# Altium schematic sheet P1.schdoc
size 381 x 305 mm; Symbol: Drawing-Symbol_A4; Company: 嘉立创EDA; Version: V1.0; Page Size: A4; @Project Name: foc; @Update Date: 2026-06-04; @Create Date: 2026-06-04; Device: Drawing-Symbol_A4; @Board Name: Board1; @Page Name: P1; @Create Time: 11:16:55; @Page Count: 1; @Page No: 1; @Schematic Name: Schematic1; @Update Time: 12:06:55; @Assembly Variant: Basic; Border: 1; Title Block Position: 3; Size: A4; Width: 1500; Height: 1200; Region Start: 1; X Region Count: 6; Y Region Count: 4; Blade Width: 10
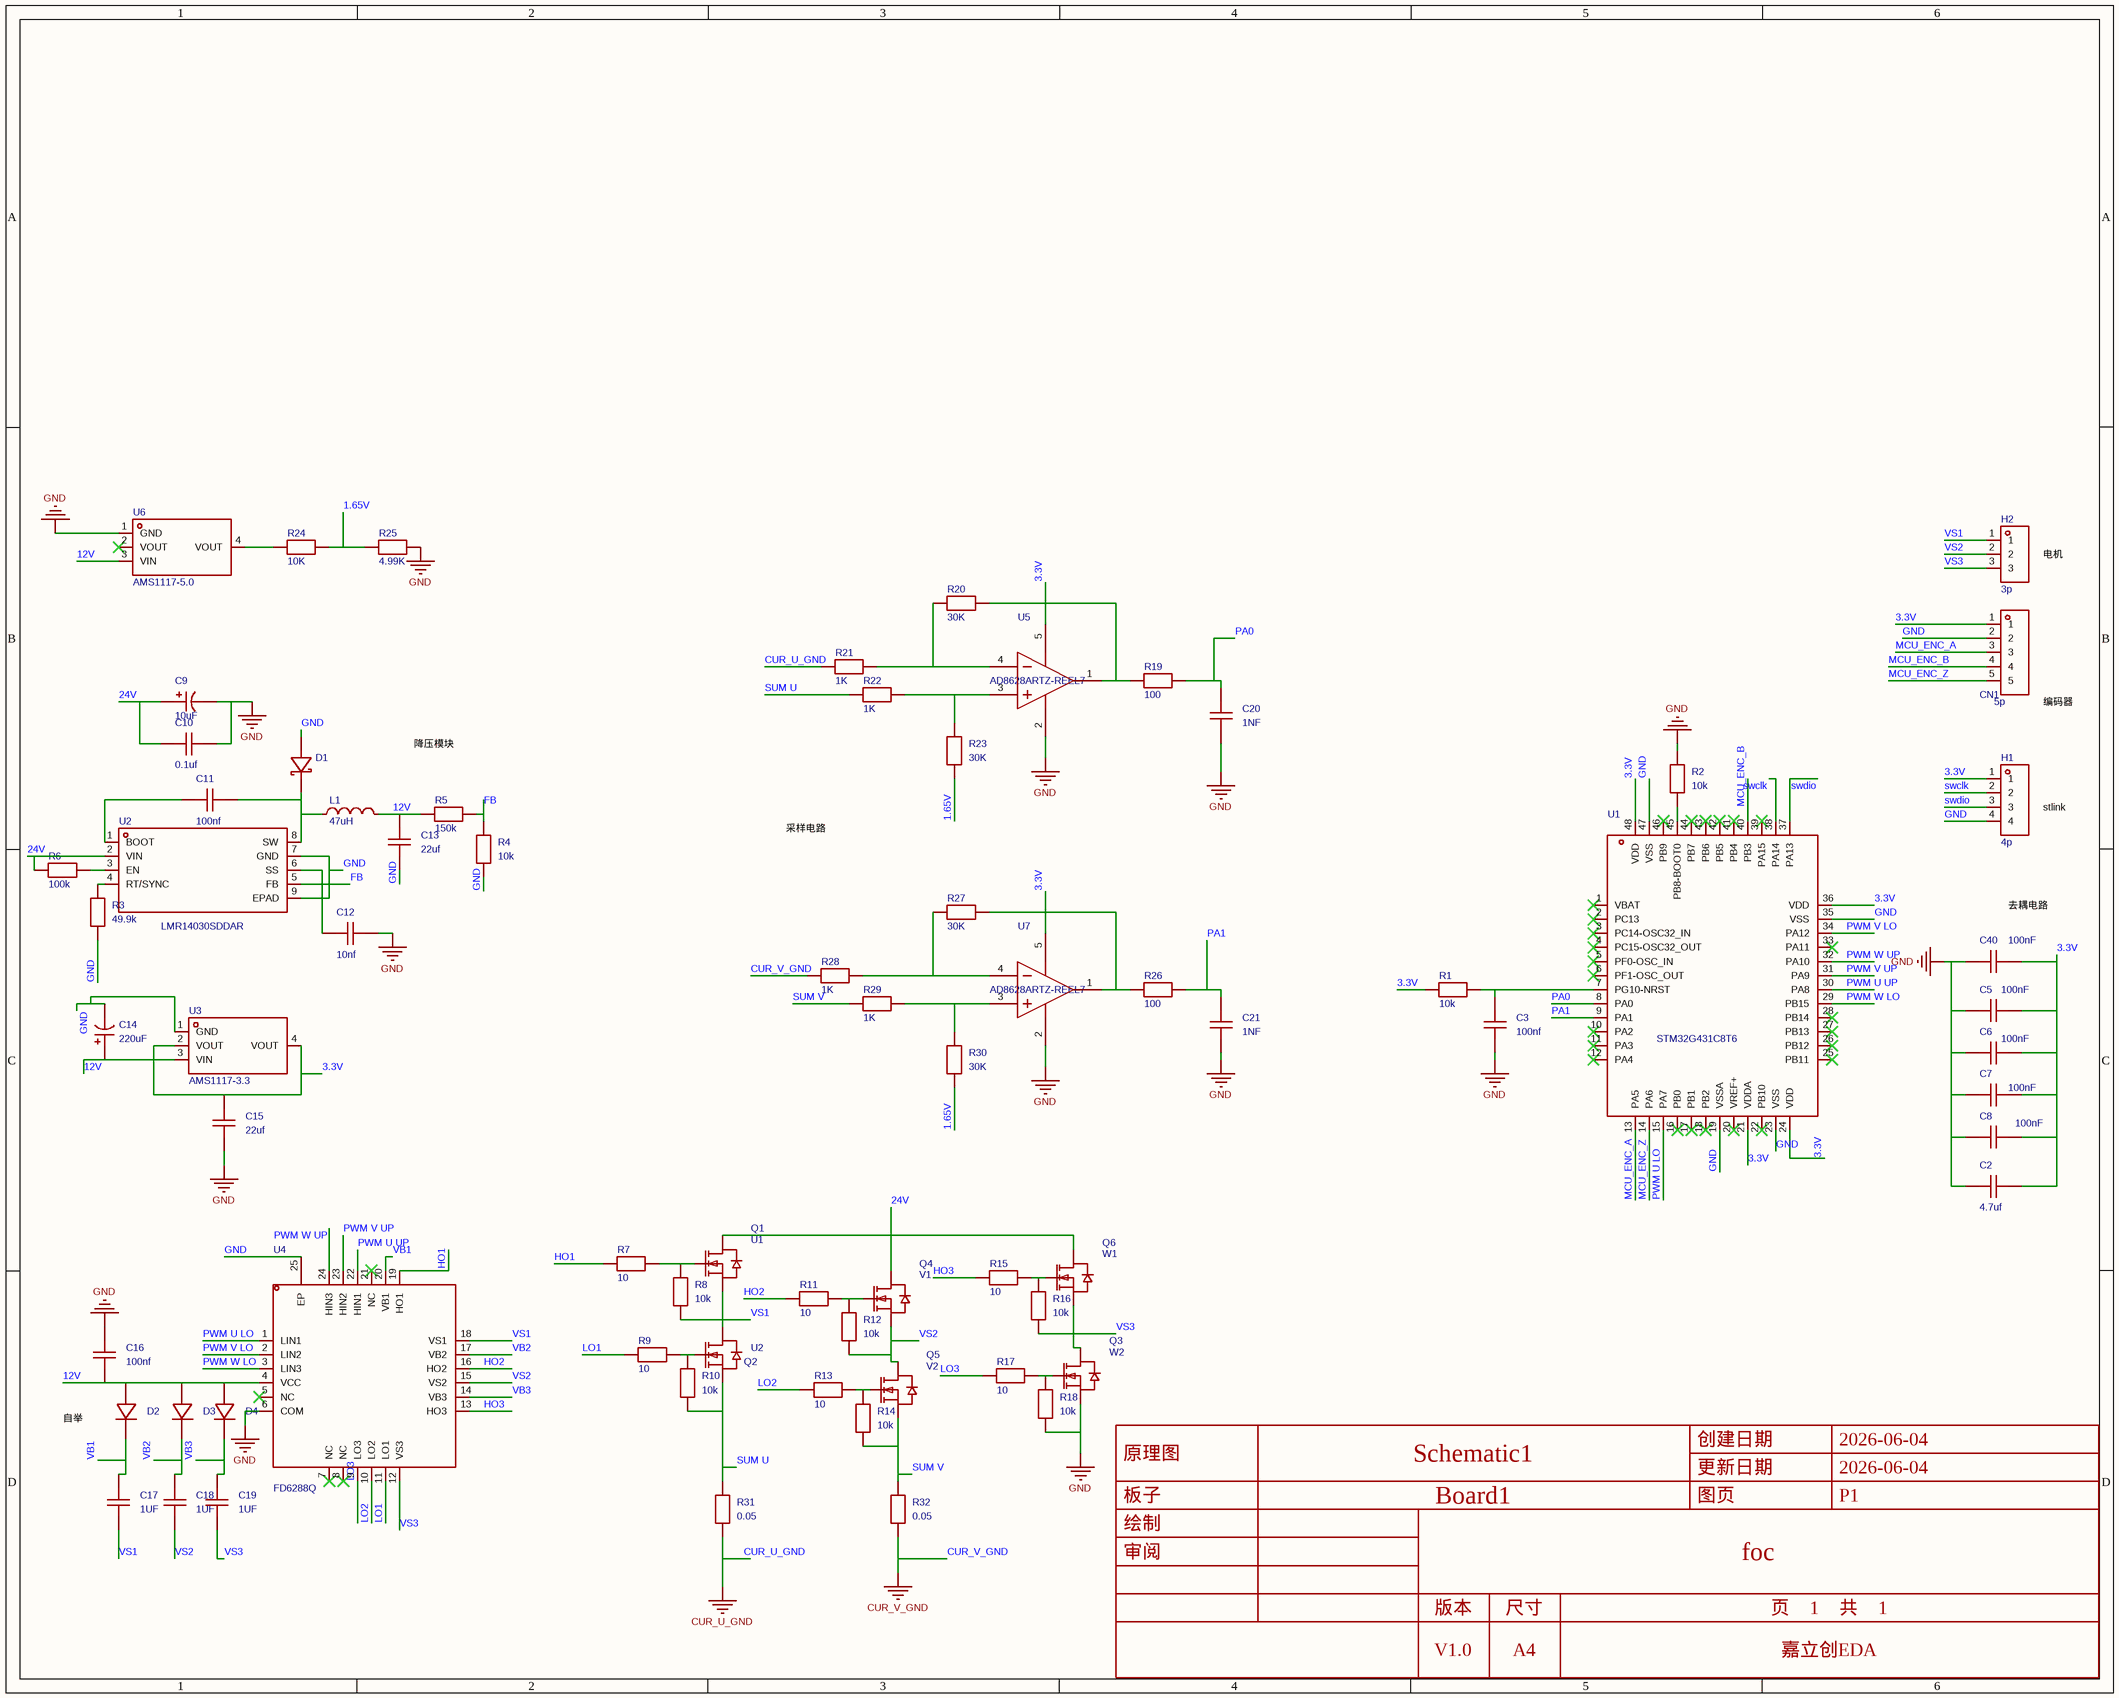
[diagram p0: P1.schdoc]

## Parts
C2  4.7uf  [C0603]
C3  100nf  [C0603]
C5  100nF  [C0603]
C6  100nF  [C0603]
C7  100nF  [C0603]
C8  100nF  [C0603]
C9  10uF  [CAP-SMD_BD6.3-L6.6-W6.6-LS7.3-FD-H7.7]
C10  0.1uf  [C0603]
C11  100nf  [C0603]
C12  10nf  [C0603]
C13  22uf  [C0603]
C14  220uF  [CAP-SMD_L7.3-W4.3-RD]
C15  22uf  [C0603]
C16  100nf  [C0603]
C17  1UF  [C0603]
C18  1UF  [C0603]
C19  1UF  [C0603]
C20  1NF  [C0603]
C21  1NF  [C0603]
C40  100nF  [C0603]
CN1  5p  [CONN-TH_5P-P2.50_WAFER-XH254Z-5A]
D1  (no value)  [SMA_L4.2-W2.6-LS5.0-RD]
D2  (no value)  [SOD-123_L2.8-W1.8-LS3.7-RD]
D3  (no value)  [SOD-123_L2.8-W1.8-LS3.7-RD]
D4  (no value)  [SOD-123_L2.8-W1.8-LS3.7-RD]
H1  4p  [HDR-TH_4P-P2.54-V-M]
H2  3p  [HDR-TH_3P-P2.54-V-M_PZ254V-11-03P]
L1  47uH  [L0603]
Q1  U1  [TO-252-2_L6.6-W6.1-P4.57-LS9.9-BR-CW]
Q2  U2  [TO-252-2_L6.6-W6.1-P4.57-LS9.9-BR-CW]
Q3  W2  [TO-252-2_L6.6-W6.1-P4.57-LS9.9-BR-CW]
Q4  V1  [TO-252-2_L6.6-W6.1-P4.57-LS9.9-BR-CW]
Q5  V2  [TO-252-2_L6.6-W6.1-P4.57-LS9.9-BR-CW]
Q6  W1  [TO-252-2_L6.6-W6.1-P4.57-LS9.9-BR-CW]
R1  10k  [R1206]
R2  10k  [R1206]
R3  49.9k  [R1206]
R4  10k  [R1206]
R5  150k  [R1206]
R6  100k  [R1206]
R7  10  [R1206]
R8  10k  [R1206]
R9  10  [R1206]
R10  10k  [R1206]
R11  10  [R1206]
R12  10k  [R1206]
R13  10  [R1206]
R14  10k  [R1206]
R15  10  [R1206]
R16  10k  [R1206]
R17  10  [R1206]
R18  10k  [R1206]
R19  100  [R1206]
R20  30K  [R1206]
R21  1K  [R1206]
R22  1K  [R1206]
R23  30K  [R1206]
R24  10K  [R1206]
R25  4.99K  [R1206]
R26  100  [R1206]
R27  30K  [R1206]
R28  1K  [R1206]
R29  1K  [R1206]
R30  30K  [R1206]
R31  0.05  [R1206]
R32  0.05  [R1206]
U1  STM32G431C8T6  [LQFP-48_L7.0-W7.0-P0.50-LS9.0-BL]
U2  LMR14030SDDAR  [SO-8_L4.9-W3.9-P1.27-LS6.0-BL-EP]
U3  AMS1117-3.3  [SOT-223-3_L6.5-W3.4-P2.30-LS7.0-BR]
U4  FD6288Q  [QFN-24_L4.0-W4.0-P0.50-BL-EP2.6]
U5  AD8628ARTZ-REEL7  [SOT-23-5_L3.0-W1.7-P0.95-LS2.8-BR]
U6  AMS1117-5.0  [SOT-223_L6.5-W3.5-P2.30-LS7.0-BR]
U7  AD8628ARTZ-REEL7  [SOT-23-5_L3.0-W1.7-P0.95-LS2.8-BR]

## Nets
CUR_U_GND: R21.1 R31.1
CUR_V_GND: R28.1 R32.1
GND: C2.1 C3.1 C5.1 C6.1 C7.1 C8.1 C9.2 C10.1 C12.1 C13.2 C14.2 C15.2 C16.1 C20.2 C21.2 C40.1 CN1.2 D1.2(+) H1.4 Q3.3(S) R2.2 R3.1 R4.1 R18.1 R25.2 U1.19(VSSA) U1.23(VSS) U1.35(VSS) U1.47(VSS) U2.7(GND) U2.9(EPAD) U3.1(GND) U4.6(COM) U4.25(EP) U5.2(-V) U6.1(GND) U7.2(-V)
1.65V: R23.2 R24.2 R25.1 R30.2
3.3V: C2.2 C5.2 C6.2 C7.2 C8.2 C15.1 C40.2 CN1.1 H1.1 R1.1 U1.21(VDDA) U1.24(VDD) U1.36(VDD) U1.48(VDD) U3.2(VOUT) U3.4(VOUT) U5.5(+V) U7.5(+V)
12V: C13.1 C14.1 C16.2 D2.2(A) D3.2(A) D4.2(A) L1.2 R5.1 U3.3(VIN) U4.4(VCC) U6.3(VIN)
24V: C9.1 C10.2 Q1.2(D) Q4.2(D) Q6.2(D) R6.1 U2.2(VIN)
FB: R4.2 R5.2 U2.5(FB)
HO1: R7.2 U4.19(HO1)
HO2: R11.2 U4.16(HO2)
HO3: R15.2 U4.13(HO3)
LO1: R9.2 U4.11(LO1)
LO2: R13.2 U4.10(LO2)
LO3: R17.2 U4.9(LO3)
MCU_ENC_A: CN1.3 U1.13(PA5)
MCU_ENC_B: CN1.4 U1.40(PB3)
MCU_ENC_Z: CN1.5 U1.14(PA6)
PA0: C20.1 R19.1 U1.8(PA0)
PA1: C21.1 R26.1 U1.9(PA1)
PWM U LO: U1.15(PA7) U4.1(LIN1)
PWM U UP: U1.30(PA8) U4.22(HIN1)
PWM V LO: U1.34(PA12) U4.2(LIN2)
PWM V UP: U1.31(PA9) U4.23(HIN2)
PWM W LO: U1.29(PB15) U4.3(LIN3)
PWM W UP: U1.32(PA10) U4.24(HIN3)
SUM U: Q2.3(S) R10.1 R22.2 R31.2
SUM V: Q5.3(S) R14.1 R29.2 R32.2
swclk: H1.2 U1.38(PA14)
swdio: H1.3 U1.37(PA13)
VB1: C17.1 D2.1(K) U4.20(VB1)
VB2: C18.1 D3.1(K) U4.17(VB2)
VB3: C19.1 D4.1(K) U4.14(VB3)
VS1: C17.2 H2.1 Q1.3(S) Q2.2(D) R8.1 U4.18(VS1)
VS2: C18.2 H2.2 Q4.3(S) Q5.2(D) R12.1 U4.15(VS2)
VS3: C19.2 H2.3 Q3.2(D) Q6.3(S) R16.1 U4.12(VS3)
NetC3_2: C3.2 R1.2 U1.7(PG10-NRST)
NetC11_1: C11.1 D1.1(-) L1.1 U2.8(SW)
NetC11_2: C11.2 U2.1(BOOT)
NetC12_2: C12.2 U2.6(SS)
NetQ1_1: Q1.1(G) R7.1 R8.2
NetQ2_1: Q2.1(G) R9.1 R10.2
NetQ3_1: Q3.1(G) R17.1 R18.2
NetQ4_1: Q4.1(G) R11.1 R12.2
NetQ5_1: Q5.1(G) R13.1 R14.2
NetQ6_1: Q6.1(G) R15.1 R16.2
NetR2_1: R2.1 U1.45(PB8-BOOT0)
NetR3_2: R3.2 U2.4(RT/SYNC)
NetR6_2: R6.2 U2.3(EN)
NetR19_2: R19.2 R20.1 U5.1(OUT)
NetR20_2: R20.2 R21.2 U5.4(-IN)
NetR22_1: R22.1 R23.1 U5.3(+IN)
NetR24_1: R24.1 U6.4(VOUT)
NetR26_2: R26.2 R27.1 U7.1(OUT)
NetR27_2: R27.2 R28.2 U7.4(-IN)
NetR29_1: R29.1 R30.1 U7.3(+IN)

Not connected (* = marked no-connect by the designer): U1 1(VBAT)* 2(PC13)* 3(PC14-OSC32_IN)* 4(PC15-OSC32_OUT)* 5(PF0-OSC_IN)* 6(PF1-OSC_OUT)* 10(PA2)* 11(PA3)* 12(PA4)* 16(PB0)* 17(PB1)* 18(PB2)* 20(VREF+)* 22(PB10)* 25(PB11)* 26(PB12)* 27(PB13)* 28(PB14)* 33(PA11)* 39(PA15)* 41(PB4)* 42(PB5)* 43(PB6)* 44(PB7)* 46(PB9)*; U4 5(NC)* 7(NC)* 8(NC)* 21(NC)*; U6 2(VOUT)*

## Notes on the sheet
- (near H2) 电机
- (near CN1) 编码器
- 降压模块
- (near H1) stlink
- 采样电路
- (near C40) 去耦电路
- 自举

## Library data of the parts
C2 C3 C5-C8 C10-C13 C15-C21 C40 = CAP_0603: Symbol: Capacitance; ConvertToPcb: yes; ModelId: ac125912035d415993ca9572d50418b10819f05c4eef4c71ace90d822a990e87; ModelName: C0603_L1.6-W0.8-H0.8; ModelTransform: 62.992,31.496,0,0,0,0,0,0,0
C9 = JVJ50V100M6x8: 容值:100uF;精度:±20%;额定电压:50V;纹波电流:140mA@120Hz;; Manufacturer: JIERR(捷而瑞); AddInBom: yes; ModelId: ccbda52dceed4b139172c40f75c9da3f0819f05c4eef4c71ace90d822a990e87; ModelTransform: 287.401,259.842,0,0,0,0,0,0,0; Tolerance: ±20%; Voltage Rating: 50V; Lifetime: 2000hrs@105℃
C14 = TA10R0L220AR30: 容值:220uF;精度:-30%~+10%;额定电压:10V;等效串联电阻(ESR):30mΩ@100kHz;; Manufacturer: JIERR(捷而瑞); AddInBom: yes; ModelId: 8a83722128254b9eb218ad9f7deffbeb0819f05c4eef4c71ace90d822a990e87; ModelTransform: 288.976,169.291,0,180,0,0,0,0,0; Voltage Rating: 10V; Current - Leakage: 220uA@20℃,2min; Ripple Current: 2.2A@100kHz
CN1 = WAFER-XH254Z-5AL: 插针结构:1x5P;间距:2.54mm;安装方式:直插;参考系列:XH;总PIN数:5P;排数:1;每排PIN数:5;额定电流:3A;触头材质:黄铜;工作温度:-25℃~+85℃;; Manufacturer: HANBO(汉博); AddInBom: yes; ModelId: 79b08f5d88c847b5a19023d5cc77e9220819f05c4eef4c71ace90d822a990e87; ModelTransform: 590.554,232.28296,0,0,0,0,0,15.748,-133.858; Pins Structure: 1x5P; Pitch: 2.54mm; Reference Series: XH; Number of PINs Per Row: 5; Current Rating: 3A; Voltage Rating: 250V; Plastic Material: PA66; Flame Retardant Rating: UL94V-0
D1 = SS34-E: 正向压降(Vf):600mV@3A;直流反向耐压(Vr):40V;整流电流:3A;; Manufacturer: MDD(辰达半导体); AddInBom: yes; ModelId: d417df25dbfe400cb6fd237f79dd97960819f05c4eef4c71ace90d822a990e87; ModelTransform: 196.85,101.181,0,0,0,0,0,0,0; Voltage - DC Reverse(Vr): 40V; Current - Rectified: 3A; Reverse Leakage Current (Ir): 500uA@40V; Operating Junction Temperature Range: -55℃~+125℃; Non-Repetitive Peak Forward Surge Current: 75A
D2-D4 = 1N4148W-E3-08: 二极管配置:1个独立式;正向压降(Vf):1.2V@100mA;直流反向耐压(Vr):75V;整流电流:150mA;反向恢复时间(Trr):4ns;; Manufacturer: VISHAY(威世); AddInBom: yes; ModelId: 7884390a25fb4c08947731ebfba7e3f80819f05c4eef4c71ace90d822a990e87; ModelTransform: 144.8816,62.992,0,0,0,0,0,0,0; Diode Configuration: 1个独立式; Voltage - DC Reverse(Vr): 75V; Current - Rectified: 150mA; Pd - Power Dissipation: 350mW; Reverse Leakage Current (Ir): 100uA@100V; Reverse Recovery Time (trr): 4ns; Non-Repetitive Peak Forward Surge Current: 2A
H1 = PZ254V-11-04P: 插针结构:1x4P;间距:2.54mm;行距:-;圆针/方针:方针;安装方式:直插;排数:单排;总PIN位数:4P;额定电流:3A;额定电压:250V;配合针长度:6mm;塑高:2.5mm;端接针长度:3mm;触头材质:-;工作温度:-40℃~+105℃;颜色:黑色;; Manufacturer: XFCN(兴飞); Symbol: PZ254V-11-04P_C2691448; AddInBom: yes; ModelId: 112f4d05e8d64e99ab9a333894bea4f90819f05c4eef4c71ace90d822a990e87; ModelName: HDR-TH_4P-P2.54-M-LI-1X4P; ModelTransform: 399.999,104.7242,0,0,0,0,0,0,-118.11; Pin Structure: 1x4P; Pitch: 2.54mm; Circluar Pins/Square Pins: 方针; Current Rating: 3A; Voltage Rating (Max): 250V
H2 = PZ254V-11-03P: 插针结构:1x3P;间距:2.54mm;行距:-;圆针/方针:方针;安装方式:直插;排数:单排;总PIN位数:3P;额定电流:3A;额定电压:250V;配合针长度:6mm;塑高:2.5mm;端接针长度:3mm;工作温度:-40℃~+105℃;颜色:黑色;; Manufacturer: XFCN(兴飞); Symbol: PZ254V-11-03P_C2937625; AddInBom: yes; ModelId: bd28a638fbd247be9398fd5d39c366ec0819f05c4eef4c71ace90d822a990e87; ModelTransform: 300.3931,100,0,0,0,0,0,0,-118.11; Pin Structure: 1x3P; Pitch: 2.54mm; Circluar Pins/Square Pins: 方针; Current Rating: 3A; Voltage Rating (Max): 250V
L1 = L_0603: Symbol: SDFL1608S100KTF; AddInBom: yes; ModelId: 2bc5ec593d464d6ba9807aec0b5673c20819f05c4eef4c71ace90d822a990e87; ModelName: L0603_L1.6-W0.8-H0.5_BEAD; ModelTransform: 62.992,31.496,0,180,0,0,0.094,0.629,0
Q1-Q6 = NCEP40T11K: 数量:1个N沟道;漏源电压(Vdss):40V;连续漏极电流(Id):110A;导通电阻(RDS(on)):3.3mΩ@4.5V,55A;耗散功率(Pd):150W;阈值电压(Vgs(th)):1.2V;; Manufacturer: NCE(无锡新洁能); AddInBom: yes; ModelId: ce57f84d66384067af8a68020b6de06d0819f05c4eef4c71ace90d822a990e87; ModelName: TO-252-2L-3P_L6.6-W6.1-H2.3-LS10.1-P4.6; ModelTransform: 259.842,390.52442,0,90,0,0,-39.39,0,0; Number: 1个N沟道; Drain to Source Voltage: 40V; Current - Continuous Drain(Id): 110A; Pd - Power Dissipation: 150W; Gate Threshold Voltage (Vgs(th)): 1.2V; Gate Charge(Qg): 60nC@20V; Input Capacitance(Ciss): 3.51nF@20V; Reverse Transfer Capacitance (Crss@Vds): 60pF
R1-R32 = RE1206F1R000: 电阻类型:采样电阻；合金电阻;阻值:0Ω;精度:±1%;功率:1W;安装方式:贴片;; Manufacturer: JIERR(捷而瑞); AddInBom: yes; ModelId: 89a1f13db2384da588040e0b3c55bf660819f05c4eef4c71ace90d822a990e87; ModelName: R1206_L3.2-W1.6-H0.6; ModelTransform: 125.984,62.992,0,0,0,0,0,0,0; Tolerance: ±1%; Power(Watts): 1W
U1 = STM32G431C8T6: CPU内核:ARM-M系列;CPU最大主频:170MHz;应用领域:-;; Manufacturer: ST(意法半导体); AddInBom: yes; ModelId: 093be70396ff421eb2cdb946d5311efc0819f05c4eef4c71ace90d822a990e87; ModelName: LQFP-48_L7.0-W7.0-H1.4-LS9.0-P0.50; ModelTransform: 354.331,354.331,0,0,0,0,0,0,0; CPU Maximum Speed: 170MHz; Program Storage Size: 64KB; Program Memory Type: FLASH; Number of I/O: 38; ADC (Bit): 12bit; Voltage - Supply: 1.71V~3.6V
U2 = LMR14030SDDAR: 功能类型:降压型;工作电压:4V~40V;输出电压:800mV~28V;输出电流:3.5A;输出类型:可调;; Manufacturer: TI(德州仪器); AddInBom: yes; ModelId: 756fba4e187a48c69a2c935cd5c4465b0819f05c4eef4c71ace90d822a990e87; ModelName: SO-8_L4.9-W3.9-H1.5-LS5.9-P1.27; ModelTransform: 240.39054,192.913,0,270,0,0,0.004,-0.002,0; Function: 降压型; Voltage - Supply: 4V~40V; Output Current: 3.5A; Frequency - Switching: 2.5MHz; Synchronous Rectifier: 否; Number of Outputs: 1; Topology: 降压式; Quiescent Current: 40uA; Switch tube (built-in/external): 内置; Output Type: 可调
U3 = AMS1117-3.3_C6186: 输出类型:固定;工作电压:15V;输出电压:3.3V;输出电流:1A;电源纹波抑制比(PSRR):72dB@(120Hz);输出极性:正极;; Manufacturer: AMS; AddInBom: yes; ModelId: 925194bf9823436183a3e0b978a8d0760819f05c4eef4c71ace90d822a990e87; ModelName: SOT-223-4P_L6.5-W3.5-H1.6-LS7.0-P2.30; ModelTransform: 279.89794,255.905,0,180,0,0,-3.9385,-0.0005,0; Output Type: 固定; Voltage - Supply: 15V; Output Voltage: 3.3V; Output Current: 1A; Voltage Dropout: 1.1V@(800mA); standby current: 5mA; Noise: 0.003%Vout; Output Configuration: 正极; Number of Outputs: 1
U4 = FD6288Q: 驱动配置:三相;负载类型:MOSFET；IGBT;驱动通道数:3;灌电流(IOL):1.8A;拉电流(IOH):1.5A;工作电压:5V~20V;上升时间(tr):12ns;下降时间(tf):12ns;; Manufacturer: Fortior Tech(峰岹); Symbol: FD6288Q_C328453; AddInBom: yes; ModelId: 1e6a51e223ba431598528b34e5bdfcc90819f05c4eef4c71ace90d822a990e87; ModelName: QFN-24_L4.0-W4.0-H0.9-P0.50; ModelTransform: 157.48,157.48,0,90,0,0,0,0,0; Driven Configuration: 三相; Number of Drivers: 3; Current - Output Low(IOL): 1.8A; Current - Output High(IOH): 1.5A; Voltage - Supply: 5V~20V; Rise Time: 12ns; Propagation Delay tpLH: 300ns; Propagation Delay tpHL: 100ns; Input Logic Level - High: 2.7V; Input Logic Level - Low: 800mV; Quiescent Current(Iq): 330uA
U5 U7 = AD8628ARTZ-REEL7: 放大器数:单路;增益带宽积(GBP):2.5MHz;输入偏置电流(Ib):30pA;输入失调电压(Vos):1uV;压摆率(SR):1V/us;带宽(-3db):2.5MHz;轨到轨:-;; Manufacturer: ADI(亚德诺); AddInBom: yes; ModelId: 0a2a1b8f50944f73965918ad6e5fe1670819f05c4eef4c71ace90d822a990e87; ModelName: SOT-23-5_L2.9-W1.6-H1.1-LS2.8-P0.95; ModelTransform: 114.173,109.636,0,180,0,0,0,0,0; Number of Channels: 单路; Gain Bandwidth Product: 2.5MHz; Ib - Input Bias Current: 30pA; Vos - Input Offset Voltage: 1uV; Slew Rate: 1V/us; Quiescent Current per Amplifier: 850uA
U6 = AMS1117-5.0_C6187: 输出类型:固定;工作电压:15V;输出电压:5V;输出电流:1A;电源纹波抑制比(PSRR):60dB;输出极性:正极;; Manufacturer: AMS; AddInBom: yes; ModelId: 925194bf9823436183a3e0b978a8d0760819f05c4eef4c71ace90d822a990e87; ModelName: SOT-223-4P_L6.5-W3.5-H1.6-LS7.0-P2.30; ModelTransform: 279.89794,255.905,0,180,0,0,0.0005,0.0005,0; Output Type: 固定; Voltage - Supply: 15V; Output Voltage: 5V; Output Current: 1A; Power Supply Rejection Ratio (PSRR): 60dB; Voltage Dropout: 1.3V; Output Configuration: 正极; Number of Outputs: 1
